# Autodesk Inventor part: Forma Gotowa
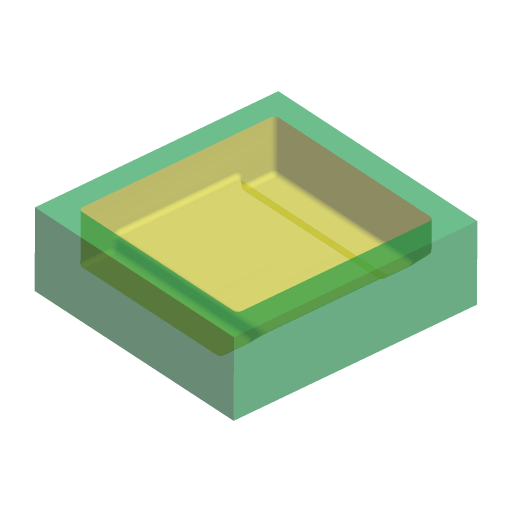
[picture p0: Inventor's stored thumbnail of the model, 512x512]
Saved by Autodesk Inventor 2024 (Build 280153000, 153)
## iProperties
Company: ATC
Shininess: 20.0
Length Units: 11269
Angle Units: 11279
Time Units: 11290
Mass Units: 11283
Length Display Precision: 3
Angle Display Precision: 2
Compacted: True
Created: 2023-03
Part Number: Forma Gotowa
Document SubType Name: Modeling
Designer: Andrzej Jaskulski
Material: Kurs-AJ
Density: 1 g/cm^3
Appearance: Przezroczyste - zielone 1
Checked By: A.J.
Engr Approved By: Andrzej Jaskulski
Mfg Approved By: Andrzej Jaskulski
Authority: A.J.
Density: 0.0
Volumn: 0.0
Area: 0.0
PropertySet Name: Model Information
Control State: 0
Master: False
Checked Out: False
Title: A.J.: Kurs R2024-MEP
Author: Andrzej Jaskulski
Revision Number: 1/24
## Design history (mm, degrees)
derived "Odlew w Formie.iam"
  feature "Forma.ipt:1" dims "d0" = 10
  feature "Odlew Surowy.ipt:1" dims "d0" = 10
node "Bryła1"
node "Korpusy bryłowe"
node "Korpusy powierzchniowe"
other parameters: "SZEROKOŚĆ" = 85 [user parameter], "NADDATEK" = 3 [user parameter], "PROMIEŃ" = 2 [user parameter]
